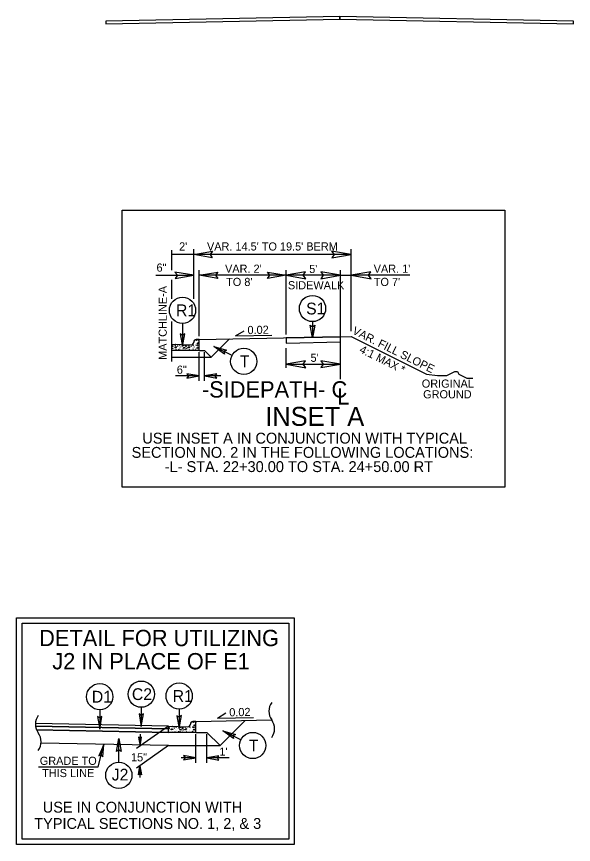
# Model space of a CAD drawing. Extents: x 1487909 to 1489267, y 497866 to 499814.
# Drawn here: x 1489059 to 1489110.3, y 498243.3 to 498319.5 of the extents above; entities that cross this region are included whole.
import ezdxf

# ---------------------------------------------------------------- set-up
doc = ezdxf.new("R2010")
doc.units = 0
for name, color, linetype in [('Default', 7, 'Continuous'), ('Old_Level_10', 7, 'Continuous'), ('Prop Conc 4in Sidewalk', 7, 'Continuous'), ('Prop Dimension', 7, 'Continuous'), ('Prop Dimension Text', 7, 'Continuous'), ('Prop Shade Light', 7, 'Continuous'), ('Prop Terminator CELL', 7, 'Continuous'), ('Sheet Typical CELL', 7, 'Continuous'), ('Typical Curb CELL', 7, 'Continuous'), ('Typical Detail Wedge2 CELL', 7, 'Continuous'), ('Typical Hinge Slope Arterial CELL', 7, 'Continuous'), ('Typical Hinge Slope Interstate CELL', 7, 'Continuous'), ('Typical ID Circle CELL', 7, 'Continuous'), ('Typical Pavement Slope CELL', 7, 'Continuous'), ('Typical Pavement Slope Information CELL', 7, 'Continuous'), ('Typical Terminator CELL', 7, 'Continuous'), ('Typical Text ID Circle CELL', 7, 'Continuous'), ('Typical Text Label CELL', 7, 'Continuous')]:
    doc.layers.add(name, color=color, linetype=linetype)

msp = doc.modelspace()

# ---------------------------------------------------------------- linework, layer by layer
at = {"layer": 'Old_Level_10'}
for p, q in [((1489073.032, 498253.964), (1489060.79, 498254.209)), ((1489060.874, 498253.874), (1489073.032, 498253.631)), ((1489073.032, 498253.631), (1489073.032, 498253.964))]:
    msp.add_line(p, q, dxfattribs=at)
msp.add_arc((1489062.17, 498254.38), 1.391, 187.04495, 201.30991, dxfattribs=at)
at = {"layer": 'Prop Conc 4in Sidewalk'}
for p, q in [((1489083.837, 498289.945), (1489088.837, 498290.045)), ((1489083.837, 498289.945), (1489083.837, 498289.464)), ((1489088.837, 498289.564), (1489088.837, 498290.045)), ((1489083.837, 498289.464), (1489088.837, 498289.564))]:
    msp.add_line(p, q, dxfattribs=at)
at = {"layer": 'Prop Dimension'}
for p, q in [((1489073.337, 498296.178), (1489073.337, 498298.007)), ((1489075.337, 498297.607), (1489073.337, 498297.607)), ((1489075.337, 498293.54), (1489075.337, 498298.107)), ((1489089.837, 498297.607), (1489075.337, 498297.607)), ((1489089.837, 498290.567), (1489089.837, 498298.107)), ((1489075.837, 498290.111), (1489075.837, 498296.168)), ((1489083.837, 498290.255), (1489083.837, 498296.168)), ((1489088.837, 498290.567), (1489088.837, 498296.168)), ((1489071.842, 498295.697), (1489075.337, 498295.697)), ((1489073.338, 498293.54), (1489073.338, 498295.275)), ((1489083.837, 498295.697), (1489075.837, 498295.697)), ((1489083.837, 498295.697), (1489075.837, 498295.697)), ((1489088.837, 498295.697), (1489083.837, 498295.697)), ((1489088.837, 498295.697), (1489089.837, 498295.697)), ((1489095.228, 498295.697), (1489089.837, 498295.697)), ((1489073.338, 498287.761), (1489073.338, 498291.459)), ((1489088.837, 498286.131), (1489088.837, 498291.165)), ((1489075.837, 498285.979), (1489075.837, 498288.633)), ((1489076.337, 498285.979), (1489076.337, 498288.633)), ((1489083.837, 498287.193), (1489083.837, 498288.981)), ((1489083.837, 498287.513), (1489088.837, 498287.513)), ((1489075.837, 498286.439), (1489073.675, 498286.439)), ((1489077.823, 498286.439), (1489076.337, 498286.439)), ((1489075.531, 498250.825), (1489075.531, 498253.478)), ((1489076.531, 498250.825), (1489076.531, 498253.478)), ((1489066.548, 498250.441), (1489067.064, 498252.524)), ((1489075.531, 498251.284), (1489074.194, 498251.284)), ((1489078.599, 498251.284), (1489076.531, 498251.284)), ((1489061.075, 498250.441), (1489066.548, 498250.441))]:
    msp.add_line(p, q, dxfattribs=at)
for centre, start, end in [((1489083.65, 498255.578), 144.51477, 215.48523), ((1489062.17, 498254.38), 144.51477, 215.48523), ((1489062.17, 498254.38), 144.51477, 215.48523), ((1489081.384, 498253.963), 324.51477, 35.48523), ((1489059.905, 498252.765), 324.51477, 35.48523), ((1489059.905, 498252.765), 324.51477, 35.48523)]:
    msp.add_arc(centre, 1.391, start, end, dxfattribs=at)
at = {"layer": 'Prop Shade Light'}
for p, q in [((1489088.767, 498319.515), (1489067.267, 498319.085)), ((1489067.267, 498318.835), (1489088.767, 498319.265)), ((1489067.267, 498319.085), (1489067.267, 498318.835)), ((1489088.767, 498319.265), (1489088.767, 498319.515)), ((1489110.267, 498319.085), (1489088.767, 498319.515)), ((1489088.767, 498319.515), (1489088.767, 498319.265)), ((1489088.767, 498319.265), (1489110.267, 498318.835)), ((1489110.267, 498318.835), (1489110.267, 498319.085)), ((1489088.837, 498290.045), (1489083.837, 498289.945)), ((1489083.837, 498289.945), (1489083.837, 498289.464)), ((1489088.837, 498289.564), (1489088.837, 498290.045)), ((1489083.837, 498289.464), (1489088.837, 498289.564)), ((1489073.032, 498254.214), (1489060.782, 498254.459)), ((1489060.79, 498254.209), (1489073.032, 498253.964)), ((1489073.032, 498253.964), (1489073.032, 498254.214))]:
    msp.add_line(p, q, dxfattribs=at)
msp.add_arc((1489062.17, 498254.38), 1.391, 176.72034, 187.04495, dxfattribs=at)
at = {"layer": 'Prop Terminator CELL'}
for points in [[(1489077.047, 498297.313), (1489075.337, 498297.607), (1489077.057, 498297.911), (1489076.838, 498297.607)], [(1489088.037, 498297.297), (1489089.837, 498297.607), (1489088.027, 498297.927), (1489088.257, 498297.607)], [(1489073.627, 498295.402), (1489075.337, 498295.697), (1489073.618, 498296.001), (1489073.836, 498295.697)], [(1489077.547, 498295.402), (1489075.837, 498295.697), (1489077.557, 498296.001), (1489077.338, 498295.697)], [(1489082.127, 498295.991), (1489083.837, 498295.697), (1489082.118, 498295.393), (1489082.336, 498295.697)], [(1489085.637, 498296.007), (1489083.837, 498295.697), (1489085.647, 498295.377), (1489085.417, 498295.697)], [(1489087.037, 498295.387), (1489088.837, 498295.697), (1489087.027, 498296.017), (1489087.257, 498295.697)], [(1489091.637, 498296.007), (1489089.837, 498295.697), (1489091.647, 498295.377), (1489091.417, 498295.697)], [(1489085.637, 498287.823), (1489083.837, 498287.513), (1489085.647, 498287.193), (1489085.417, 498287.513)], [(1489087.037, 498287.203), (1489088.837, 498287.513), (1489087.027, 498287.833), (1489087.257, 498287.513)], [(1489074.712, 498286.245), (1489075.837, 498286.439), (1489074.706, 498286.639), (1489074.849, 498286.439)], [(1489077.462, 498286.632), (1489076.337, 498286.439), (1489077.468, 498286.239), (1489077.324, 498286.439)], [(1489066.981, 498251.385), (1489067.064, 498252.524), (1489066.597, 498251.474), (1489066.826, 498251.565)], [(1489074.406, 498251.09), (1489075.531, 498251.284), (1489074.4, 498251.484), (1489074.544, 498251.284)], [(1489077.656, 498251.478), (1489076.531, 498251.284), (1489077.663, 498251.084), (1489077.519, 498251.284)]]:
    msp.add_lwpolyline(points, close=True, dxfattribs=at)
at = {"layer": 'Sheet Typical CELL'}
for points in [[(1489068.745, 498301.682), (1489103.949, 498301.682), (1489103.949, 498276.209), (1489068.745, 498276.209)], [(1489059.045, 498264.175), (1489084.594, 498264.175), (1489084.594, 498243.312), (1489059.045, 498243.312)], [(1489059.545, 498263.675), (1489084.094, 498263.675), (1489084.094, 498243.812), (1489059.545, 498243.812)]]:
    msp.add_lwpolyline(points, close=True, dxfattribs=at)
at = {"layer": 'Typical Curb CELL'}
for p, q in [((1489073.337, 498288.785), (1489073.337, 498289.369)), ((1489073.337, 498289.369), (1489075.087, 498289.296)), ((1489073.598, 498289.025), (1489073.684, 498289.145)), ((1489073.684, 498289.145), (1489073.718, 498289.031)), ((1489074.363, 498288.974), (1489074.426, 498289.088)), ((1489074.426, 498289.088), (1489074.529, 498289.013)), ((1489074.847, 498289.025), (1489074.933, 498289.145)), ((1489074.933, 498289.145), (1489074.967, 498289.031)), ((1489075.337, 498289.535), (1489075.337, 498289.546)), ((1489075.837, 498289.785), (1489075.577, 498289.785)), ((1489075.612, 498288.974), (1489075.674, 498289.088)), ((1489075.646, 498289.452), (1489075.663, 498289.361)), ((1489075.8, 498289.407), (1489075.646, 498289.452)), ((1489075.663, 498289.361), (1489075.8, 498289.407)), ((1489075.674, 498289.088), (1489075.778, 498289.013)), ((1489075.837, 498288.785), (1489075.837, 498289.785)), ((1489075.837, 498288.785), (1489073.337, 498288.785)), ((1489073.718, 498289.031), (1489073.598, 498289.025)), ((1489074.529, 498289.013), (1489074.363, 498288.974)), ((1489074.967, 498289.031), (1489074.847, 498289.025)), ((1489075.778, 498289.013), (1489075.612, 498288.974)), ((1489073.032, 498253.631), (1489073.032, 498254.214)), ((1489073.032, 498254.214), (1489074.782, 498254.141)), ((1489075.031, 498254.381), (1489075.031, 498254.391)), ((1489075.531, 498254.631), (1489075.271, 498254.631)), ((1489075.341, 498254.297), (1489075.357, 498254.207)), ((1489075.495, 498254.253), (1489075.341, 498254.297)), ((1489075.357, 498254.207), (1489075.495, 498254.253)), ((1489075.531, 498253.631), (1489075.531, 498254.631)), ((1489075.531, 498253.631), (1489073.032, 498253.631)), ((1489073.292, 498253.87), (1489073.378, 498253.99)), ((1489073.413, 498253.877), (1489073.292, 498253.87)), ((1489073.378, 498253.99), (1489073.413, 498253.877)), ((1489074.058, 498253.819), (1489074.12, 498253.934)), ((1489074.223, 498253.859), (1489074.058, 498253.819)), ((1489074.12, 498253.934), (1489074.223, 498253.859)), ((1489074.542, 498253.87), (1489074.627, 498253.99)), ((1489074.662, 498253.877), (1489074.542, 498253.87)), ((1489074.627, 498253.99), (1489074.662, 498253.877)), ((1489075.306, 498253.819), (1489075.369, 498253.934)), ((1489075.472, 498253.859), (1489075.306, 498253.819)), ((1489075.369, 498253.934), (1489075.472, 498253.859))]:
    msp.add_line(p, q, dxfattribs=at)
for centre in [(1489073.354, 498289.122), (1489073.371, 498289.219), (1489073.427, 498289.185), (1489073.535, 498289.31), (1489073.632, 498289.225), (1489073.678, 498289.327), (1489073.827, 498289.264), (1489073.855, 498289.162), (1489074.032, 498289.248), (1489074.049, 498289.298), (1489074.129, 498289.105), (1489074.306, 498289.27), (1489074.426, 498289.219), (1489074.603, 498289.122), (1489074.62, 498289.219), (1489074.676, 498289.185), (1489074.785, 498289.279), (1489074.881, 498289.225), (1489075.076, 498289.264), (1489075.104, 498289.162), (1489075.281, 498289.248), (1489075.298, 498289.298), (1489075.378, 498289.105), (1489075.555, 498289.27), (1489075.607, 498289.709), (1489075.675, 498289.219), (1489075.772, 498289.493), (1489075.824, 498289.675), (1489073.348, 498288.814), (1489073.411, 498288.98), (1489073.507, 498289.025), (1489073.558, 498288.791), (1489073.718, 498288.86), (1489073.924, 498288.837), (1489074.004, 498289.077), (1489074.038, 498288.923), (1489074.095, 498288.808), (1489074.272, 498288.871), (1489074.443, 498288.831), (1489074.597, 498288.814), (1489074.66, 498288.98), (1489074.756, 498289.025), (1489074.807, 498288.791), (1489074.967, 498288.86), (1489075.173, 498288.837), (1489075.253, 498289.077), (1489075.287, 498288.923), (1489075.344, 498288.808), (1489075.521, 498288.871), (1489075.692, 498288.831), (1489073.065, 498254.065), (1489073.121, 498254.031), (1489073.23, 498254.155), (1489073.327, 498254.071), (1489073.373, 498254.173), (1489073.521, 498254.11), (1489073.726, 498254.094), (1489073.744, 498254.144), (1489074, 498254.116), (1489074.12, 498254.065), (1489074.314, 498254.065), (1489074.37, 498254.031), (1489074.479, 498254.125), (1489074.576, 498254.071), (1489074.77, 498254.11), (1489074.976, 498254.094), (1489074.993, 498254.144), (1489075.249, 498254.116), (1489075.301, 498254.555), (1489075.369, 498254.065), (1489075.467, 498254.338), (1489075.518, 498254.521), (1489073.042, 498253.66), (1489073.048, 498253.968), (1489073.105, 498253.825), (1489073.201, 498253.871), (1489073.253, 498253.637), (1489073.412, 498253.705), (1489073.549, 498254.008), (1489073.618, 498253.682), (1489073.698, 498253.922), (1489073.732, 498253.768), (1489073.789, 498253.654), (1489073.824, 498253.951), (1489073.966, 498253.717), (1489074.137, 498253.677), (1489074.291, 498253.66), (1489074.297, 498253.968), (1489074.354, 498253.825), (1489074.45, 498253.871), (1489074.502, 498253.637), (1489074.662, 498253.705), (1489074.799, 498254.008), (1489074.867, 498253.682), (1489074.947, 498253.922), (1489074.981, 498253.768), (1489075.038, 498253.654), (1489075.073, 498253.951), (1489075.215, 498253.717), (1489075.386, 498253.677)]:
    msp.add_circle(centre, 0.00802, dxfattribs=at)
for centre, start, end in [((1489075.097, 498289.535), 267.61554, 0), ((1489075.577, 498289.546), 90, 180), ((1489074.792, 498254.381), 267.61554, 0), ((1489075.271, 498254.391), 90, 180)]:
    msp.add_arc(centre, 0.24, start, end, dxfattribs=at)
at = {"layer": 'Typical Detail Wedge2 CELL'}
for p, q in [((1489073.032, 498254.214), (1489070.068, 498252.138)), ((1489070.399, 498253.454), (1489070.399, 498252.37)), ((1489073.032, 498252.405), (1489070.068, 498250.33)), ((1489070.388, 498250.554), (1489070.388, 498249.47))]:
    msp.add_line(p, q, dxfattribs=at)
at = {"layer": 'Typical Hinge Slope Arterial CELL'}
msp.add_line((1489089.837, 498290.065), (1489096.765, 498286.601), dxfattribs=at)
msp.add_lwpolyline([(1489096.765, 498286.601), (1489097.75, 498286.479), (1489097.997, 498286.479), (1489098.367, 498286.479), (1489098.613, 498286.479), (1489098.859, 498286.601), (1489099.106, 498286.725), (1489099.352, 498286.849), (1489099.599, 498286.849), (1489099.722, 498286.601), (1489099.969, 498286.479), (1489100.215, 498286.355), (1489100.461, 498286.232), (1489100.708, 498286.232), (1489100.954, 498286.232), (1489101.026, 498286.232)], dxfattribs=at)
at = {"layer": 'Typical ID Circle CELL'}
for p, q in [((1489086.268, 498291.432), (1489086.268, 498289.937)), ((1489074.305, 498291.266), (1489074.305, 498289.142)), ((1489078.862, 498288.315), (1489077.204, 498289.139)), ((1489066.691, 498255.702), (1489066.691, 498253.923)), ((1489070.514, 498255.938), (1489070.514, 498254.158)), ((1489073.999, 498255.768), (1489073.999, 498253.988)), ((1489079.683, 498252.956), (1489078.025, 498253.78)), ((1489068.449, 498250.885), (1489068.449, 498253.051))]:
    msp.add_line(p, q, dxfattribs=at)
for centre in [(1489074.305, 498292.474), (1489086.268, 498292.64), (1489079.944, 498287.777), (1489066.691, 498256.911), (1489070.514, 498257.146), (1489073.999, 498256.976), (1489080.765, 498252.418), (1489068.449, 498249.677)]:
    msp.add_circle(centre, 1.208, dxfattribs=at)
at = {"layer": 'Typical Pavement Slope CELL'}
for p, q in [((1489075.837, 498289.785), (1489089.837, 498290.065)), ((1489078.619, 498289.841), (1489076.95, 498288.172)), ((1489075.837, 498288.785), (1489076.337, 498288.785)), ((1489076.337, 498288.785), (1489076.95, 498288.172)), ((1489073.337, 498288.172), (1489076.95, 498288.172)), ((1489073.032, 498254.214), (1489060.782, 498254.459)), ((1489073.032, 498253.964), (1489060.79, 498254.209)), ((1489075.531, 498254.631), (1489082.517, 498254.771)), ((1489080.075, 498254.722), (1489077.758, 498252.405)), ((1489073.032, 498253.631), (1489060.874, 498253.874)), ((1489075.531, 498253.631), (1489076.531, 498253.631)), ((1489076.531, 498253.631), (1489077.758, 498252.405)), ((1489073.032, 498252.405), (1489061.29, 498252.639)), ((1489073.032, 498252.405), (1489077.758, 498252.405))]:
    msp.add_line(p, q, dxfattribs=at)
at = {"layer": 'Typical Pavement Slope Information CELL'}
for p, q in [((1489079.196, 498290.121), (1489079.979, 498290.595)), ((1489079.196, 498290.121), (1489082.513, 498290.188)), ((1489077.52, 498254.939), (1489078.303, 498255.413)), ((1489077.52, 498254.939), (1489080.836, 498255.006))]:
    msp.add_line(p, q, dxfattribs=at)
at = {"layer": 'Typical Terminator CELL'}
for points in [[(1489086.47, 498291.109), (1489086.268, 498289.937), (1489086.06, 498291.116), (1489086.268, 498290.966)], [(1489086.47, 498291.109), (1489086.268, 498289.937), (1489086.06, 498291.116), (1489086.268, 498290.966)], [(1489074.103, 498290.314), (1489074.305, 498289.142), (1489074.513, 498290.321), (1489074.305, 498290.171)], [(1489078.164, 498288.437), (1489077.204, 498289.139), (1489078.352, 498288.801), (1489078.125, 498288.681)], [(1489066.49, 498255.094), (1489066.691, 498253.923), (1489066.9, 498255.101), (1489066.691, 498254.951)], [(1489070.312, 498255.33), (1489070.514, 498254.158), (1489070.722, 498255.336), (1489070.514, 498255.186)], [(1489073.798, 498255.16), (1489073.999, 498253.988), (1489074.208, 498255.166), (1489073.999, 498255.016)], [(1489078.984, 498253.078), (1489078.025, 498253.78), (1489079.173, 498253.442), (1489078.946, 498253.323)], [(1489068.247, 498251.879), (1489068.449, 498253.051), (1489068.657, 498251.873), (1489068.449, 498252.023)], [(1489070.258, 498253.191), (1489070.399, 498252.37), (1489070.545, 498253.195), (1489070.399, 498253.09)], [(1489070.247, 498249.734), (1489070.388, 498250.554), (1489070.534, 498249.729), (1489070.388, 498249.834)]]:
    msp.add_lwpolyline(points, close=True, dxfattribs=at)

# ---------------------------------------------------------------- texts
at = {"layer": 'Default'}
msp.add_text('DETAIL FOR UTILIZING', height=1.5, rotation=359.99993, dxfattribs=at).set_placement((1489061.118, 498261.565))
at = {"layer": 'Prop Dimension Text'}
for s, p in [("2'", (1489073.998, 498297.981)), ("VAR. 14.5' TO 19.5' BERM", (1489076.56, 498297.981)), ('6"', (1489071.918, 498296.033)), ("VAR. 2'", (1489078.222, 498295.931)), ("5'", (1489085.961, 498295.908)), ("VAR. 1'", (1489091.894, 498295.931)), ("TO 8'", (1489078.322, 498294.713)), ("TO 7'", (1489091.904, 498294.713)), ('SIDEWALK', (1489084.006, 498294.408)), ("5'", (1489086.087, 498287.733)), ('6"', (1489073.786, 498286.637)), ("1'", (1489077.7, 498251.483)), ('GRADE TO', (1489061.181, 498250.636)), ('15"', (1489069.572, 498250.961)), ('THIS LINE', (1489061.399, 498249.511))]:
    msp.add_text(s, height=0.75, dxfattribs=at).set_placement(p)
at = {"layer": 'Typical Hinge Slope Arterial CELL'}
for s, rotation, p in [('MATCHLINE-A', 90, (1489072.86, 498287.918)), ('VAR. FILL SLOPE', 333.46576, (1489089.864, 498290.354)), ('4:1 MAX *', 333.46576, (1489090.518, 498288.63))]:
    msp.add_text(s, height=0.75, rotation=rotation, dxfattribs=at).set_placement(p)
for s, height, p in [('ORIGINAL', 0.75, (1489096.318, 498285.355)), ('GROUND', 0.75, (1489096.444, 498284.372)), ('USE INSET A IN CONJUNCTION WITH TYPICAL', 1, (1489070.613, 498280.209)), ('SECTION NO. 2 IN THE FOLLOWING LOCATIONS:', 1, (1489069.627, 498278.899)), ('-L- STA. 22+30.00 TO STA. 24+50.00 RT', 1, (1489072.674, 498277.588))]:
    msp.add_text(s, height=height, dxfattribs=at).set_placement(p)
at = {"layer": 'Typical Hinge Slope Interstate CELL'}
for s, p in [('-SIDEPATH- C', (1489076.09, 498284.448)), ('L', (1489088.547, 498283.8))]:
    msp.add_text(s, height=1.5, dxfattribs=at).set_placement(p)
at = {"layer": 'Typical Pavement Slope CELL'}
msp.add_text('INSET A', height=1.75, dxfattribs=at).set_placement((1489081.92, 498281.841))
at = {"layer": 'Typical Pavement Slope Information CELL'}
for p in [(1489080.294, 498290.282), (1489078.618, 498255.1)]:
    msp.add_text('0.02', height=0.75, rotation=1.14574, dxfattribs=at).set_placement(p)
at = {"layer": 'Typical Text ID Circle CELL'}
for s, height, p in [('R1', 1.0817, (1489073.712, 498291.933)), ('S1', 1.0817, (1489085.681, 498292.099)), ('T', 1.082, (1489079.588, 498287.236)), ('D1', 1.0817, (1489065.971, 498256.37)), ('C2', 1.0817, (1489069.654, 498256.605)), ('R1', 1.0817, (1489073.406, 498256.435)), ('T', 1.082, (1489080.409, 498251.878)), ('J2', 1.0817, (1489067.801, 498249.198))]:
    msp.add_text(s, height=height, dxfattribs=at).set_placement(p)
at = {"layer": 'Typical Text Label CELL'}
msp.add_text('J2 IN PLACE OF E1', height=1.5, rotation=360, dxfattribs=at).set_placement((1489062.328, 498259.429))
for s, p in [('USE IN CONJUNCTION WITH ', (1489061.452, 498246.241)), ('TYPICAL SECTIONS NO. 1, 2, & 3', (1489060.667, 498244.741))]:
    msp.add_text(s, height=1, dxfattribs=at).set_placement(p)

doc.saveas('drawing.dxf')
